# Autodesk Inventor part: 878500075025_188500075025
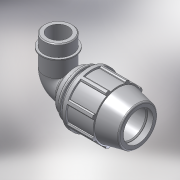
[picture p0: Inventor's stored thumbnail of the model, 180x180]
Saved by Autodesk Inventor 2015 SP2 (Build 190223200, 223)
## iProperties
Created: 2017-02
Part Number: 878500075025_188500075025
Material: PVC-Piping
Description: PLASSON 90° ELBOW MALE ADAPTOR 75-2.1/2"
Document SubType Name: Modeling
Designer: KIM
Mass: 92.6774 g
Surface Area: 199.44 cm^2
Volume: 66.1981 cm^3
Density: 1.4 g/cm^3
Appearance: Smooth - White
Author: KIM
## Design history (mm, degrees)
derived "87850.ipt"
feature "Solid1::87850.ipt"
tag "TaggingFeature1"
body "Solid1"
other parameters: "d2" = 75, "d4" = 17.25, "d5" = 51.75, "d7" = 132, "d9" = 29.57143, "d11" = 6.9, "d13" = 120 deg, "d14" = 97.5, "d15" = 12 deg, "d16" = 114.84, "d18" = 3.75, "d19" = 35 deg, "d20" = 17.5 deg, "d21" = 122.76, "d23" = 0, "d25" = 360 deg, "d27" = 2.64, "d33" = 1.5, "d42" = 76.59, "d43" = 3.96, "d46" = 2.25, "d51" = 207, "d68" = 13.8, "d72" = 105, "d73" = 72.226, "d75" = 83.0599, "d76" = 50.5582, "d77" = 33, "d79" = 28.8904, "d80" = 2.16678, "d83" = 0, "d84" = 0, "d91" = 99, "d93" = 137, "d94" = 72.226, "d95" = 50.5582, "d96" = 13.8, "d97" = 50 deg, "d98" = 3.45, "d99" = 111.3948, "d100" = 3.45, "d101" = 3.45, "d102" = 8.8, "d103" = 0, "d_" = 75, "E_" = 132, "A_" = 207, "l_" = 137, "A_1" = 105, "G_" = 72.226
